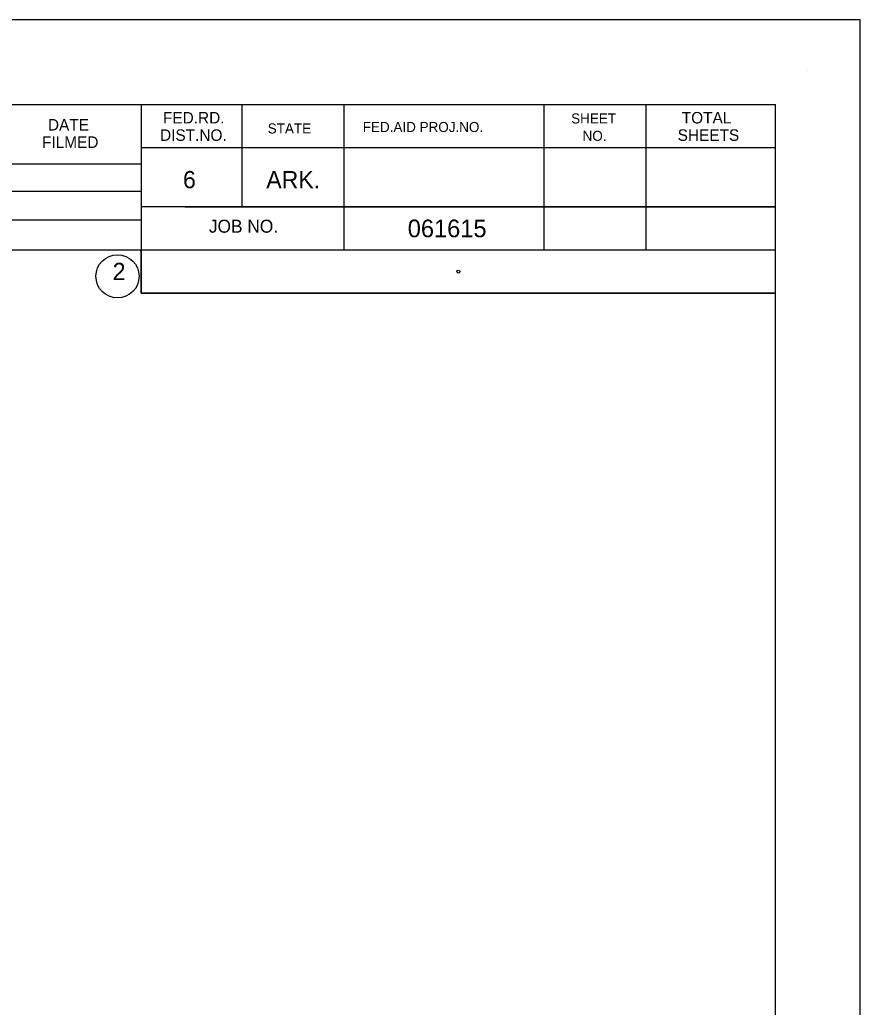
# Model space of a CAD drawing. Extents: x 1448008.9 to 1448047, y 2057056.5 to 2057079.8.
# Drawn here: x 1448037.23 to 1448042.95, y 2057073.11 to 2057079.82 of the extents above; entities that cross this region are included whole.
import ezdxf

# ---------------------------------------------------------------- set-up
doc = ezdxf.new("R2010")
doc.units = 0
doc.layers.add('1', color=7, linetype='Continuous')
doc.layers.add('NO PLOT CELL', color=7, linetype='Continuous')

msp = doc.modelspace()

# ---------------------------------------------------------------- linework, layer by layer
at = {"layer": '1'}
for p, q in [((1448042.5875, 2057079.4716), (1448042.5875, 2057079.4716)), ((1448010.4614, 2057079.2409), (1448042.3686, 2057079.2409)), ((1448038.0586, 2057079.2409), (1448038.0586, 2057077.9609)), ((1448038.7426, 2057079.2409), (1448038.7426, 2057078.5469)), ((1448039.4366, 2057079.2409), (1448039.4366, 2057078.2529)), ((1448040.7946, 2057079.2409), (1448040.7946, 2057078.2529)), ((1448041.4886, 2057079.2409), (1448041.4886, 2057078.2529)), ((1448042.3686, 2057058.3945), (1448042.3686, 2057079.2409)), ((1448042.3686, 2057078.9489), (1448042.3686, 2057078.9489)), ((1448042.3686, 2057078.9469), (1448038.0586, 2057078.9469)), ((1448034.1426, 2057078.8389), (1448038.0586, 2057078.8389)), ((1448034.1426, 2057078.6529), (1448038.0586, 2057078.6529)), ((1448042.3686, 2057078.5469), (1448038.0586, 2057078.5469)), ((1448038.3546, 2057078.5469), (1448042.3686, 2057078.5469)), ((1448034.1426, 2057078.4589), (1448038.0586, 2057078.4589)), ((1448042.3686, 2057078.2529), (1448034.1426, 2057078.2529)), ((1448038.0586, 2057078.2529), (1448034.1426, 2057078.2529)), ((1448038.0586, 2057077.9609), (1448038.0586, 2057078.2529)), ((1448038.0586, 2057077.9609), (1448042.3686, 2057077.9609)), ((1448042.3686, 2057077.9609), (1448038.0586, 2057077.9609)), ((1448042.3686, 2057058.3945), (1448042.3686, 2057077.9609))]:
    msp.add_line(p, q, dxfattribs=at)
msp.add_lwpolyline([(1448042.9454, 2057079.8177), (1448008.9454, 2057079.8177), (1448008.9454, 2057057.8177), (1448042.9454, 2057057.8177)], close=True, dxfattribs=at)
msp.add_circle((1448037.8973, 2057078.0745), 0.1467, dxfattribs=at)
at = {"layer": 'NO PLOT CELL'}
msp.add_circle((1448040.2136, 2057078.1069), 0.01, dxfattribs=at)

# ---------------------------------------------------------------- texts
at = {"layer": '1'}
for s, height, p in [('FED.RD.', 0.07819, (1448038.2064, 2057079.1129)), ('SHEET', 0.0684, (1448040.9804, 2057079.1129)), ('TOTAL', 0.07819, (1448041.7324, 2057079.1129)), ('DATE', 0.07819, (1448037.4244, 2057079.0649)), ('STATE', 0.0684, (1448038.9184, 2057079.0449)), ('FED.AID PROJ.NO.', 0.0684, (1448039.5644, 2057079.0549)), ('FILMED', 0.07819, (1448037.3844, 2057078.9469)), ('DIST.NO.', 0.07819, (1448038.1864, 2057078.9949)), ('NO.', 0.0684, (1448041.0584, 2057078.9949)), ('SHEETS', 0.07819, (1448041.7044, 2057078.9949)), ('6', 0.1172, (1448038.3424, 2057078.6729)), ('ARK.', 0.11723, (1448038.9084, 2057078.6729)), ('JOB NO.', 0.08792, (1448038.5184, 2057078.3709)), ('061615', 0.12, (1448039.87, 2057078.3399)), ('2', 0.1172, (1448037.8644, 2057078.0489))]:
    msp.add_text(s, height=height, dxfattribs=at).set_placement(p)

doc.saveas('drawing.dxf')
